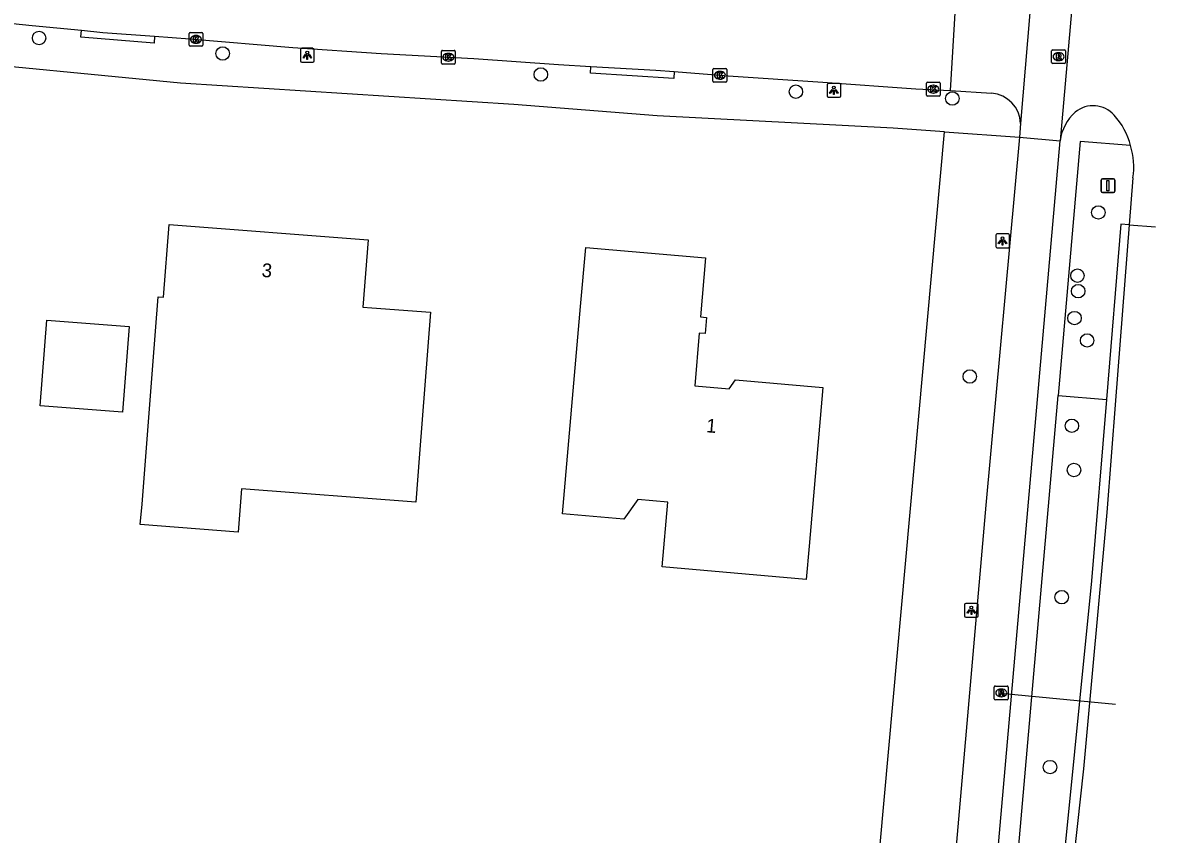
# Model space of a CAD drawing. Extents: x 161486 to 162249, y 379484 to 380829.
# Drawn here: x 162131.8 to 162214, y 380302.1 to 380361 of the extents above; entities that cross this region are included whole.
import ezdxf

# ---------------------------------------------------------------- set-up
doc = ezdxf.new("R2010")
doc.units = 0
for name, color, linetype in [('IMGEO_Berm_open', 7, 'Continuous'), ('IMGEO_Boom', 7, 'Continuous'), ('IMGEO_Duiker', 7, 'Continuous'), ('IMGEO_Fietspad_gesloten', 7, 'Continuous'), ('IMGEO_Groenvoorziening', 7, 'Continuous'), ('IMGEO_Hek', 7, 'Continuous'), ('IMGEO_Kolk', 7, 'Continuous'), ('IMGEO_Lichtpunt', 7, 'Continuous'), ('IMGEO_Pand', 7, 'Continuous'), ('IMGEO_Pand_nummerreeks', 7, 'Continuous'), ('IMGEO_Rijbaan_lokaal_gesloten', 7, 'Continuous'), ('IMGEO_Rijbaan_lokaal_open', 7, 'Continuous'), ('IMGEO_Rioolput', 7, 'Continuous'), ('IMGEO_Verkeersbordpaal', 7, 'Continuous'), ('IMGEO_Voetpad_open', 7, 'Continuous')]:
    doc.layers.add(name, color=color, linetype=linetype)

msp = doc.modelspace()

# ---------------------------------------------------------------- linework, layer by layer
at = {"layer": 'IMGEO_Berm_open'}
for points in [[(162212.116, 380346.342), (162211.506, 380346.392), (162210.466, 380333.645)], [(162210.466, 380333.645), (162209.375, 380320.485), (162208.503, 380311.757), (162208.138, 380308.103), (162206.95, 380296.206), (162205.423, 380285.635), (162202.786, 380274.134), (162194.634, 380248.881)]]:
    msp.add_lwpolyline(points, dxfattribs=at)
at = {"layer": 'IMGEO_Boom'}
for centre in [(162132.962, 380359.901), (162146.291, 380358.777), (162169.394, 380357.252), (162187.914, 380356.003), (162199.272, 380355.51), (162209.874, 380347.236), (162208.357, 380342.646), (162208.407, 380341.52), (162208.141, 380339.566), (162209.06, 380337.942), (162200.54, 380335.324), (162207.954, 380331.746), (162208.106, 380328.533), (162207.216, 380319.303), (162206.369, 380306.967)]:
    msp.add_circle(centre, 0.489, dxfattribs=at)
at = {"layer": 'IMGEO_Duiker'}
msp.add_lwpolyline([(162211.111, 380311.51), (162202.795, 380312.298)], dxfattribs=at)
at = {"layer": 'IMGEO_Fietspad_gesloten'}
for points in [[(162204.216, 380353.696), (162204.142, 380352.708)], [(162204.142, 380352.708), (162201.716, 380325.976), (162198.736, 380291.798)], [(162201.642, 380290.031), (162207.11, 380352.439)], [(162204.142, 380352.708), (162207.11, 380352.439)]]:
    msp.add_lwpolyline(points, dxfattribs=at)
at = {"layer": 'IMGEO_Groenvoorziening'}
for points in [[(162169.78, 380257.051), (162183.403, 380255.226), (162185.545, 380261.095), (162190.445, 380275.834), (162192.139, 380280.435), (162198.701, 380353.085)], [(162206.947, 380333.937), (162210.466, 380333.645)]]:
    msp.add_lwpolyline(points, dxfattribs=at)
at = {"layer": 'IMGEO_Hek'}
msp.add_lwpolyline([(162183.403, 380255.226), (162185.545, 380261.095), (162190.445, 380275.834), (162192.139, 380280.435), (162198.701, 380353.085)], dxfattribs=at)
at = {"layer": 'IMGEO_Kolk'}
for p, q in [((162143.851, 380359.377), (162143.851, 380360.229)), ((162143.926, 380360.303), (162144.778, 380360.303)), ((162144.339, 380360.083), (162144.364, 380360.083)), ((162144.852, 380360.229), (162144.852, 380359.377)), ((162144.778, 380359.303), (162143.926, 380359.303)), ((162144.362, 380359.523), (162144.337, 380359.523)), ((162162.177, 380358.079), (162162.177, 380358.931)), ((162162.252, 380359.005), (162163.104, 380359.005)), ((162163.178, 380358.931), (162163.178, 380358.079)), ((162162.688, 380358.225), (162162.663, 380358.225)), ((162162.665, 380358.785), (162162.69, 380358.785)), ((162163.104, 380358.005), (162162.252, 380358.005)), ((162181.892, 380356.768), (162181.892, 380357.62)), ((162181.967, 380357.694), (162182.819, 380357.694)), ((162182.38, 380357.474), (162182.405, 380357.474)), ((162182.893, 380357.62), (162182.893, 380356.768)), ((162182.819, 380356.694), (162181.967, 380356.694)), ((162182.403, 380356.914), (162182.378, 380356.914)), ((162197.388, 380355.761), (162197.388, 380356.613)), ((162197.463, 380356.687), (162198.315, 380356.687)), ((162197.876, 380356.467), (162197.901, 380356.467)), ((162198.389, 380356.613), (162198.389, 380355.761)), ((162198.315, 380355.687), (162197.463, 380355.687)), ((162197.899, 380355.907), (162197.874, 380355.907))]:
    msp.add_line(p, q, dxfattribs=at)
for points in [[(162143.851, 380359.377), (162143.851, 380360.229)], [(162143.926, 380360.303), (162144.778, 380360.303)], [(162144.172, 380360.003), (162144.295, 380360.003), (162144.295, 380359.852), (162144.425, 380360.003), (162144.589, 380360.003), (162144.443, 380359.852), (162144.596, 380359.603), (162144.444, 380359.603), (162144.359, 380359.767), (162144.295, 380359.7), (162144.295, 380359.603), (162144.172, 380359.603), (162144.172, 380360.003)], [(162144.852, 380360.229), (162144.852, 380359.377)], [(162144.778, 380359.303), (162143.926, 380359.303)], [(162162.177, 380358.079), (162162.177, 380358.931)], [(162162.252, 380359.005), (162163.104, 380359.005)], [(162163.178, 380358.931), (162163.178, 380358.079)], [(162162.498, 380358.705), (162162.621, 380358.705), (162162.621, 380358.554), (162162.751, 380358.705), (162162.915, 380358.705), (162162.769, 380358.554), (162162.922, 380358.305), (162162.77, 380358.305), (162162.685, 380358.469), (162162.621, 380358.402), (162162.621, 380358.305), (162162.498, 380358.305), (162162.498, 380358.705)], [(162163.104, 380358.005), (162162.252, 380358.005)], [(162181.892, 380356.768), (162181.892, 380357.62)], [(162181.967, 380357.694), (162182.819, 380357.694)], [(162182.213, 380357.394), (162182.336, 380357.394), (162182.336, 380357.243), (162182.466, 380357.394), (162182.63, 380357.394), (162182.484, 380357.243), (162182.637, 380356.994), (162182.485, 380356.994), (162182.4, 380357.158), (162182.336, 380357.091), (162182.336, 380356.994), (162182.213, 380356.994), (162182.213, 380357.394)], [(162182.893, 380357.62), (162182.893, 380356.768)], [(162182.819, 380356.694), (162181.967, 380356.694)], [(162197.388, 380355.761), (162197.388, 380356.613)], [(162197.463, 380356.687), (162198.315, 380356.687)], [(162197.709, 380356.387), (162197.832, 380356.387), (162197.832, 380356.236), (162197.962, 380356.387), (162198.126, 380356.387), (162197.98, 380356.236), (162198.133, 380355.987), (162197.981, 380355.987), (162197.896, 380356.151), (162197.832, 380356.084), (162197.832, 380355.987), (162197.709, 380355.987), (162197.709, 380356.387)], [(162198.389, 380356.613), (162198.389, 380355.761)], [(162198.315, 380355.687), (162197.463, 380355.687)]]:
    msp.add_lwpolyline(points, dxfattribs=at)
for centre, start, end in [((162143.928, 380360.227), 91.55205, 178.44795), ((162143.928, 380360.227), 91.55205, 178.44795), ((162144.776, 380360.227), 1.55205, 88.44795), ((162144.776, 380360.227), 1.55205, 88.44795), ((162143.928, 380359.379), 181.55205, 268.44795), ((162143.928, 380359.379), 181.55205, 268.44795), ((162144.776, 380359.379), 271.55205, 358.44795), ((162144.776, 380359.379), 271.55205, 358.44795), ((162162.254, 380358.929), 91.55205, 178.44795), ((162162.254, 380358.929), 91.55205, 178.44795), ((162163.102, 380358.929), 1.55205, 88.44795), ((162163.102, 380358.929), 1.55205, 88.44795), ((162162.254, 380358.081), 181.55205, 268.44795), ((162162.254, 380358.081), 181.55205, 268.44795), ((162163.102, 380358.081), 271.55205, 358.44795), ((162163.102, 380358.081), 271.55205, 358.44795), ((162181.969, 380357.618), 91.55205, 178.44795), ((162181.969, 380357.618), 91.55205, 178.44795), ((162182.817, 380357.618), 1.55205, 88.44795), ((162182.817, 380357.618), 1.55205, 88.44795), ((162181.969, 380356.77), 181.55205, 268.44795), ((162181.969, 380356.77), 181.55205, 268.44795), ((162182.817, 380356.77), 271.55205, 358.44795), ((162182.817, 380356.77), 271.55205, 358.44795), ((162197.465, 380356.611), 91.55205, 178.44795), ((162197.465, 380356.611), 91.55205, 178.44795), ((162198.313, 380356.611), 1.55205, 88.44795), ((162198.313, 380356.611), 1.55205, 88.44795), ((162197.465, 380355.763), 181.55205, 268.44795), ((162197.465, 380355.763), 181.55205, 268.44795), ((162198.313, 380355.763), 271.55205, 358.44795), ((162198.313, 380355.763), 271.55205, 358.44795)]:
    msp.add_arc(centre, 0.0765, start, end, dxfattribs=at)
for centre, major_axis, ratio, start_param, end_param in [((162144.338, 380359.803), (-0.387, 0.002), 0.722429, 4.712389, 7.853982), ((162144.363, 380359.803), (-0.39, 0.002), 0.717154, 1.570796, 4.712389), ((162162.664, 380358.505), (-0.387, 0.002), 0.722429, 4.712389, 7.853982), ((162162.689, 380358.505), (-0.39, 0.002), 0.717154, 1.570796, 4.712389), ((162182.379, 380357.194), (-0.387, 0.002), 0.722429, 4.712389, 7.853982), ((162182.404, 380357.194), (-0.39, 0.002), 0.717154, 1.570796, 4.712389), ((162197.875, 380356.187), (-0.387, 0.002), 0.722429, 4.712389, 7.853982), ((162197.9, 380356.187), (-0.39, 0.002), 0.717154, 1.570796, 4.712389)]:
    msp.add_ellipse(centre, major_axis=major_axis, ratio=ratio, start_param=start_param, end_param=end_param, dxfattribs=at)
at = {"layer": 'IMGEO_Lichtpunt'}
for p, q in [((162151.938, 380359.056), (162151.938, 380358.249)), ((162151.938, 380359.056), (162151.938, 380358.249)), ((162152.84, 380359.151), (162152.032, 380359.151)), ((162152.84, 380359.151), (162152.032, 380359.151)), ((162152.934, 380358.249), (162152.934, 380359.056)), ((162152.934, 380358.249), (162152.934, 380359.056)), ((162152.032, 380358.155), (162152.84, 380358.155)), ((162152.032, 380358.155), (162152.84, 380358.155)), ((162190.173, 380356.505), (162190.173, 380355.698)), ((162190.173, 380356.505), (162190.173, 380355.698)), ((162191.075, 380356.6), (162190.267, 380356.6)), ((162191.075, 380356.6), (162190.267, 380356.6)), ((162191.169, 380355.698), (162191.169, 380356.505)), ((162191.169, 380355.698), (162191.169, 380356.505)), ((162190.267, 380355.604), (162191.075, 380355.604)), ((162190.267, 380355.604), (162191.075, 380355.604)), ((162202.421, 380345.578), (162202.421, 380344.771)), ((162202.421, 380345.578), (162202.421, 380344.771)), ((162203.323, 380345.673), (162202.515, 380345.673)), ((162203.323, 380345.673), (162202.515, 380345.673)), ((162203.417, 380344.771), (162203.417, 380345.578)), ((162203.417, 380344.771), (162203.417, 380345.578)), ((162202.515, 380344.677), (162203.323, 380344.677)), ((162202.515, 380344.677), (162203.323, 380344.677)), ((162200.154, 380318.754), (162200.154, 380317.947)), ((162200.154, 380318.754), (162200.154, 380317.947)), ((162201.056, 380318.849), (162200.248, 380318.849)), ((162201.056, 380318.849), (162200.248, 380318.849)), ((162201.15, 380317.947), (162201.15, 380318.754)), ((162201.15, 380317.947), (162201.15, 380318.754)), ((162200.248, 380317.853), (162201.056, 380317.853)), ((162200.248, 380317.853), (162201.056, 380317.853))]:
    msp.add_line(p, q, dxfattribs=at)
for points in [[(162152.312, 380358.72), (162152.351, 380358.692), (162152.163, 380358.43), (162152.125, 380358.457), (162152.312, 380358.72)], [(162152.414, 380358.672), (162152.461, 380358.672), (162152.461, 380358.35), (162152.414, 380358.35), (162152.414, 380358.672)], [(162152.524, 380358.692), (162152.562, 380358.719), (162152.749, 380358.457), (162152.71, 380358.429), (162152.524, 380358.692)], [(162190.547, 380356.169), (162190.586, 380356.141), (162190.398, 380355.879), (162190.36, 380355.906), (162190.547, 380356.169)], [(162190.649, 380356.121), (162190.696, 380356.121), (162190.696, 380355.799), (162190.649, 380355.799), (162190.649, 380356.121)], [(162190.759, 380356.141), (162190.797, 380356.168), (162190.984, 380355.906), (162190.945, 380355.878), (162190.759, 380356.141)], [(162202.795, 380345.242), (162202.834, 380345.214), (162202.646, 380344.952), (162202.608, 380344.979), (162202.795, 380345.242)], [(162202.897, 380345.194), (162202.944, 380345.194), (162202.944, 380344.872), (162202.897, 380344.872), (162202.897, 380345.194)], [(162203.007, 380345.214), (162203.045, 380345.241), (162203.232, 380344.979), (162203.193, 380344.951), (162203.007, 380345.214)], [(162200.528, 380318.418), (162200.567, 380318.39), (162200.379, 380318.128), (162200.341, 380318.155), (162200.528, 380318.418)], [(162200.63, 380318.37), (162200.677, 380318.37), (162200.677, 380318.048), (162200.63, 380318.048), (162200.63, 380318.37)], [(162200.74, 380318.39), (162200.778, 380318.417), (162200.965, 380318.155), (162200.926, 380318.127), (162200.74, 380318.39)]]:
    msp.add_lwpolyline(points, dxfattribs=at)
for centre in [(162152.437, 380358.854), (162190.672, 380356.303), (162202.92, 380345.376), (162200.653, 380318.552)]:
    msp.add_circle(centre, 0.0994, dxfattribs=at)
for centre, start, end in [((162152.032, 380359.056), 90, 180), ((162152.032, 380359.056), 90, 180), ((162152.84, 380359.056), 0, 90), ((162152.84, 380359.056), 0, 90), ((162152.032, 380358.249), 180, 270), ((162152.032, 380358.249), 180, 270), ((162152.84, 380358.249), 270, 0), ((162152.84, 380358.249), 270, 360), ((162190.267, 380356.505), 90, 180), ((162190.267, 380356.505), 90, 180), ((162191.075, 380356.505), 0, 90), ((162191.075, 380356.505), 0, 90), ((162190.267, 380355.698), 180, 270), ((162190.267, 380355.698), 180, 270), ((162191.075, 380355.698), 270, 0), ((162191.075, 380355.698), 270, 360), ((162202.515, 380345.578), 90, 180), ((162202.515, 380345.578), 90, 180), ((162203.323, 380345.578), 0, 90), ((162203.323, 380345.578), 0, 90), ((162202.515, 380344.771), 180, 270), ((162202.515, 380344.771), 180, 270), ((162203.323, 380344.771), 270, 0), ((162203.323, 380344.771), 270, 360), ((162200.248, 380318.754), 90, 180), ((162200.248, 380318.754), 90, 180), ((162201.056, 380318.754), 0, 90), ((162201.056, 380318.754), 0, 90), ((162200.248, 380317.947), 180, 270), ((162200.248, 380317.947), 180, 270), ((162201.056, 380317.947), 270, 0), ((162201.056, 380317.947), 270, 360)]:
    msp.add_arc(centre, 0.0946, start, end, dxfattribs=at)
at = {"layer": 'IMGEO_Pand'}
for points in [[(162142.399, 380346.371), (162156.855, 380345.248), (162156.475, 380340.37), (162157.117, 380340.32), (162161.379, 380339.989), (162160.968, 380334.698), (162160.581, 380329.713), (162160.307, 380326.19), (162147.66, 380327.173), (162147.415, 380324.022), (162140.297, 380324.576), (162140.439, 380326.054), (162141.223, 380336.133), (162141.61, 380341.117), (162141.988, 380341.088), (162142.399, 380346.371)], [(162172.65, 380344.686), (162181.351, 380343.934), (162180.98, 380339.649), (162181.428, 380339.61), (162181.327, 380338.437), (162180.896, 380338.474), (162180.564, 380334.643), (162183.061, 380334.427), (162183.522, 380335.086), (162189.868, 380334.537), (162188.87, 380323), (162188.661, 380320.589), (162178.2, 380321.494), (162178.608, 380326.202), (162176.428, 380326.391), (162175.432, 380324.965), (162170.976, 380325.351), (162171.846, 380335.402), (162172.279, 380340.401), (162172.65, 380344.686)], [(162133.522, 380339.416), (162139.493, 380338.951), (162139.009, 380332.726), (162133.038, 380333.19), (162133.522, 380339.416)]]:
    msp.add_lwpolyline(points, dxfattribs=at)
at = {"layer": 'IMGEO_Rijbaan_lokaal_gesloten'}
msp.add_lwpolyline([(162212.116, 380346.342), (162211.12, 380333.591), (162210.483, 380325.444), (162208.785, 380306.851), (162207.191, 380292.295)], dxfattribs=at)
at = {"layer": 'IMGEO_Rijbaan_lokaal_open'}
for points in [[(162205.062, 380363.773), (162204.216, 380353.696)], [(162208.079, 380363.507), (162207.11, 380352.439)], [(162199.131, 380356.1), (162199.5, 380362.124)], [(162131.065, 380360.954), (162132.47, 380360.81), (162136.039, 380360.458)], [(162136.039, 380360.458), (162137.597, 380360.305), (162141.346, 380360.03)], [(162141.346, 380360.03), (162143.914, 380359.841), (162151.391, 380359.218), (162157.806, 380358.784), (162164.523, 380358.401), (162170.67, 380357.976), (162173.036, 380357.838)], [(162173.036, 380357.838), (162177.746, 380357.563), (162179.085, 380357.457)], [(162179.085, 380357.457), (162182.993, 380357.148), (162189.86, 380356.695), (162196.626, 380356.215), (162199.131, 380356.1)], [(162199.131, 380356.1), (162202.119, 380355.887)], [(162212.39, 380349.747), (162212.116, 380346.342)], [(162212.116, 380346.342), (162214.013, 380346.192)]]:
    msp.add_lwpolyline(points, dxfattribs=at)
for centre, radius, start, end in [((162201.974, 380353.65), 2.242, 1.18675, 86.30162), ((162209.499, 380352.951), 2.035, 41.47552, 129.60908), ((162210.346, 380352.067), 3.257, 131.1611, 173.43995), ((162207.037, 380350.716), 5.36, 14.86184, 41.94374), ((162206.736, 380350.51), 5.706, 352.31077, 16.08278)]:
    msp.add_arc(centre, radius, start, end, dxfattribs=at)
at = {"layer": 'IMGEO_Rioolput'}
for p, q in [((162206.485, 380358.121), (162206.485, 380358.973)), ((162206.56, 380359.047), (162207.412, 380359.047)), ((162207.486, 380358.973), (162207.486, 380358.121)), ((162207.412, 380358.047), (162206.56, 380358.047)), ((162206.996, 380358.267), (162206.971, 380358.267)), ((162206.973, 380358.827), (162206.998, 380358.827)), ((162202.396, 380312.852), (162203.248, 380312.852)), ((162202.321, 380311.926), (162202.321, 380312.778)), ((162202.832, 380312.072), (162202.807, 380312.072)), ((162202.809, 380312.632), (162202.834, 380312.632)), ((162203.322, 380312.778), (162203.322, 380311.926)), ((162203.248, 380311.852), (162202.396, 380311.852))]:
    msp.add_line(p, q, dxfattribs=at)
for points in [[(162206.485, 380358.121), (162206.485, 380358.973)], [(162206.56, 380359.047), (162207.412, 380359.047)], [(162207.486, 380358.973), (162207.486, 380358.121)], [(162207.412, 380358.047), (162206.56, 380358.047)], [(162207.074, 380358.745), (162206.822, 380358.747), (162206.822, 380358.347)], [(162206.822, 380358.347), (162206.946, 380358.347), (162206.946, 380358.509), (162206.957, 380358.509)], [(162207, 380358.666), (162206.946, 380358.666), (162206.946, 380358.585)], [(162206.946, 380358.585), (162206.998, 380358.585)], [(162207.004, 380358.48), (162207.075, 380358.347), (162207.215, 380358.347), (162207.15, 380358.473)], [(162202.396, 380312.852), (162203.248, 380312.852)], [(162202.321, 380311.926), (162202.321, 380312.778)], [(162202.91, 380312.55), (162202.658, 380312.552), (162202.658, 380312.152)], [(162202.658, 380312.152), (162202.782, 380312.152), (162202.782, 380312.314), (162202.793, 380312.314)], [(162202.836, 380312.471), (162202.782, 380312.471), (162202.782, 380312.39)], [(162202.782, 380312.39), (162202.834, 380312.39)], [(162202.84, 380312.285), (162202.911, 380312.152), (162203.051, 380312.152), (162202.986, 380312.278)], [(162203.322, 380312.778), (162203.322, 380311.926)], [(162203.248, 380311.852), (162202.396, 380311.852)]]:
    msp.add_lwpolyline(points, dxfattribs=at)
for centre, radius, start, end in [((162206.562, 380358.971), 0.0765, 91.55205, 178.44795), ((162206.562, 380358.971), 0.0765, 91.55205, 178.44795), ((162207.41, 380358.971), 0.0765, 1.55205, 88.44795), ((162207.41, 380358.971), 0.0765, 1.55205, 88.44795), ((162206.562, 380358.123), 0.0765, 181.55205, 268.44795), ((162206.562, 380358.123), 0.0765, 181.55205, 268.44795), ((162206.956, 380358.456), 0.0533, 26.02933, 88.69889), ((162206.982, 380358.774), 0.19, 274.7715, 282.96867), ((162207.006, 380358.57), 0.0964, 77.00612, 93.18647), ((162207.02, 380358.627), 0.0378, 276.66336, 79.67722), ((162207.073, 380358.635), 0.109, 350.36119, 89.41601), ((162207.071, 380358.635), 0.112, 277.58423, 350.98172), ((162207.055, 380358.42), 0.108, 29.51342, 73.79051), ((162207.41, 380358.123), 0.0765, 271.55205, 358.44795), ((162207.41, 380358.123), 0.0765, 271.55205, 358.44795), ((162202.398, 380312.776), 0.0765, 91.55205, 178.44795), ((162202.398, 380312.776), 0.0765, 91.55205, 178.44795), ((162203.246, 380312.776), 0.0765, 1.55205, 88.44795), ((162203.246, 380312.776), 0.0765, 1.55205, 88.44795), ((162202.792, 380312.261), 0.0533, 26.02933, 88.69889), ((162202.818, 380312.579), 0.19, 274.7715, 282.96867), ((162202.842, 380312.375), 0.0964, 77.00612, 93.18647), ((162202.856, 380312.432), 0.0378, 276.66336, 79.67722), ((162202.909, 380312.44), 0.109, 350.36119, 89.41601), ((162202.907, 380312.44), 0.112, 277.58423, 350.98172), ((162202.891, 380312.225), 0.108, 29.51342, 73.79051), ((162202.398, 380311.928), 0.0765, 181.55205, 268.44795), ((162202.398, 380311.928), 0.0765, 181.55205, 268.44795), ((162203.246, 380311.928), 0.0765, 271.55205, 358.44795), ((162203.246, 380311.928), 0.0765, 271.55205, 358.44795)]:
    msp.add_arc(centre, radius, start, end, dxfattribs=at)
for centre, major_axis, ratio, start_param, end_param in [((162206.972, 380358.547), (-0.387, 0.002), 0.722429, 4.712389, 7.853982), ((162206.997, 380358.547), (-0.39, 0.002), 0.717154, 1.570796, 4.712389), ((162202.808, 380312.352), (-0.387, 0.002), 0.722429, 4.712389, 7.853982), ((162202.833, 380312.352), (-0.39, 0.002), 0.717154, 1.570796, 4.712389)]:
    msp.add_ellipse(centre, major_axis=major_axis, ratio=ratio, start_param=start_param, end_param=end_param, dxfattribs=at)
at = {"layer": 'IMGEO_Verkeersbordpaal'}
for p, q in [((162210.077, 380348.781), (162210.077, 380349.581)), ((162210.077, 380349.581), (162210.077, 380348.781)), ((162210.177, 380349.681), (162210.967, 380349.681)), ((162210.967, 380349.681), (162210.177, 380349.681)), ((162211.067, 380349.581), (162211.067, 380348.781)), ((162211.067, 380348.781), (162211.067, 380349.581)), ((162210.967, 380348.681), (162210.177, 380348.681)), ((162210.177, 380348.681), (162210.967, 380348.681))]:
    msp.add_line(p, q, dxfattribs=at)
msp.add_lwpolyline([(162210.497, 380349.556), (162210.647, 380349.556), (162210.647, 380348.806), (162210.497, 380348.806), (162210.497, 380349.556)], dxfattribs=at)
for centre, start, end in [((162210.177, 380349.581), 90, 180), ((162210.177, 380349.581), 90, 180), ((162210.967, 380349.581), 0, 90), ((162210.967, 380349.581), 360, 90), ((162210.177, 380348.781), 180, 270), ((162210.177, 380348.781), 180, 270), ((162210.967, 380348.781), 270, 0), ((162210.967, 380348.781), 270, 0)]:
    msp.add_arc(centre, 0.1, start, end, dxfattribs=at)
at = {"layer": 'IMGEO_Voetpad_open'}
for points in [[(162198.701, 380353.085), (162194.98, 380353.343), (162177.85, 380354.254), (162167.435, 380355.075), (162143.228, 380356.612), (162124.747, 380358.414), (162101.438, 380361.321), (162078.957, 380365.04), (162051.567, 380370.414), (162025.006, 380376.148), (162000, 380382.025), (161995.099, 380383.252), (161959.315, 380392.214), (161910.21, 380403.651), (161910.18, 380403.657)], [(162141.346, 380360.03), (162141.306, 380359.532), (162135.999, 380359.961), (162136.039, 380360.458)], [(162179.085, 380357.457), (162179.054, 380356.958), (162173.005, 380357.339), (162173.036, 380357.838)], [(162198.701, 380353.085), (162204.142, 380352.708)], [(162212.218, 380352.091), (162208.552, 380352.39), (162206.947, 380333.937)], [(162203.12, 380289.924), (162206.947, 380333.937)]]:
    msp.add_lwpolyline(points, dxfattribs=at)

# ---------------------------------------------------------------- texts
at = {"layer": 'IMGEO_Pand_nummerreeks'}
for s, rotation, p in [('3', 355.55958, (162149.098, 380342.56)), ('1', 355.05601, (162181.37, 380331.281))]:
    msp.add_text(s, height=1, rotation=rotation, dxfattribs=at).set_placement(p)

doc.saveas('drawing.dxf')
